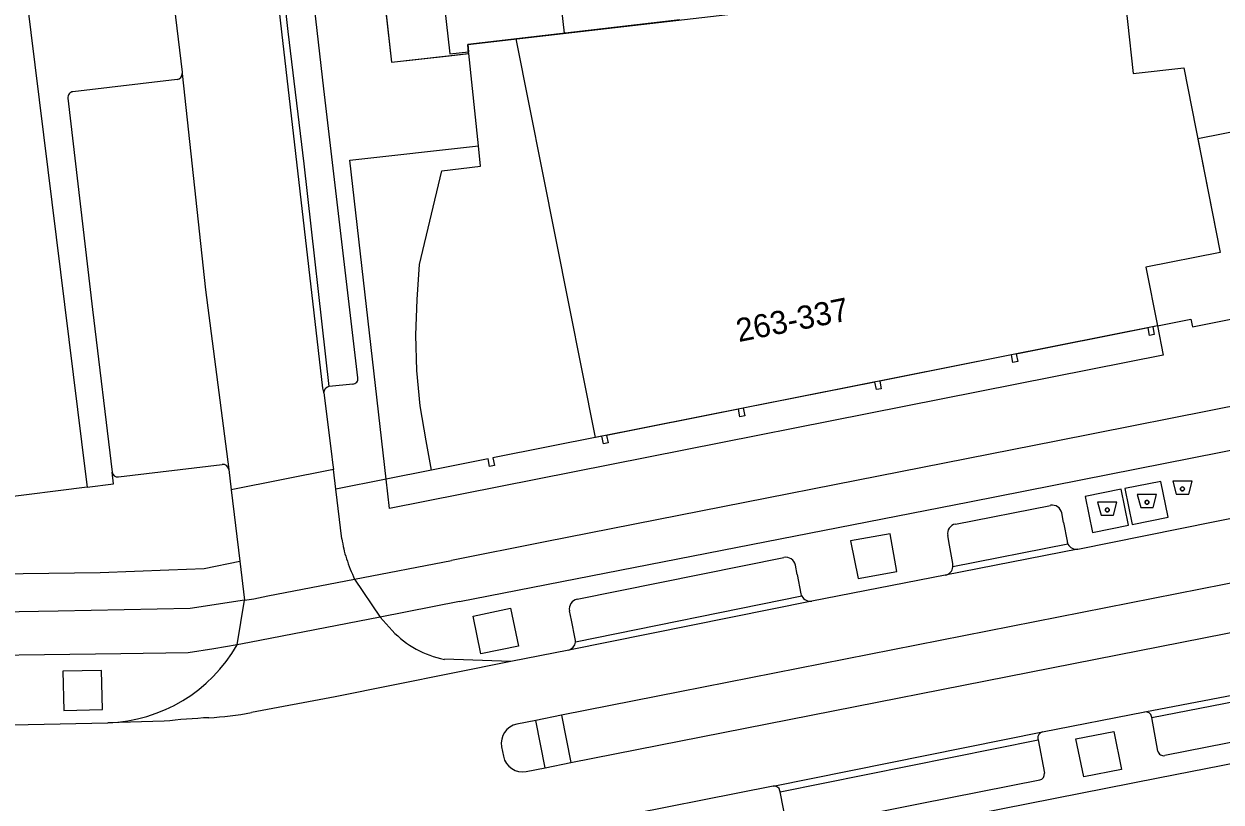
# Model space of a CAD drawing. Extents: x 194485 to 197793, y 468269 to 470822.
# Drawn here: x 194929.3 to 194991.2, y 469431.3 to 469471.6 of the extents above; entities that cross this region are included whole.
import ezdxf

# ---------------------------------------------------------------- set-up
doc = ezdxf.new("R2010")
doc.units = 0
for name, color, linetype in [('BGT begrenzing pand op maaiveld onder overbouw', 7, 'Continuous'), ('BGT grensvlak onbegroeid terreindeel', 7, 'Continuous'), ('BGT grensvlak pand deel overbouw', 7, 'Continuous'), ('BGT grensvlak pand min 1', 7, 'Continuous'), ('BGT grensvlak pand op maaiveld', 7, 'Continuous'), ('BGT grensvlak pand op maaiveld LR', 7, 'Continuous'), ('BGT grensvlak wegdeel', 7, 'Continuous'), ('BGT puntobject bak afval apart plaats', 7, 'Continuous'), ('BGT puntobject bak container', 7, 'Continuous'), ('BGT tekst huisnummerreeks', 7, 'Continuous'), ('GEM grensvlak WOZ_BRK percelen', 7, 'Continuous')]:
    doc.layers.add(name, color=color, linetype=linetype)

msp = doc.modelspace()

# ---------------------------------------------------------------- linework, layer by layer
at = {"layer": 'BGT begrenzing pand op maaiveld onder overbouw'}
for points in [[(194950.361, 469448.517), (194950.079, 469450.033), (194949.768, 469451.838), (194949.59, 469453.666), (194949.552, 469455.509), (194949.617, 469457.349), (194949.729, 469459.155), (194950.897, 469464.015), (194952.893, 469464.243), (194952.782, 469465.307)], [(194987.908, 469455.976), (194987.662, 469455.927), (194987.74, 469455.535), (194987.495, 469455.486), (194987.417, 469455.878), (194980.6, 469454.524), (194980.678, 469454.132), (194980.433, 469454.083), (194980.355, 469454.475), (194973.538, 469453.121), (194973.616, 469452.729), (194973.371, 469452.68), (194973.293, 469453.072), (194966.476, 469451.718), (194966.554, 469451.326), (194966.309, 469451.277), (194966.231, 469451.669), (194959.414, 469450.315), (194959.492, 469449.923), (194959.247, 469449.874), (194959.169, 469450.266), (194953.529, 469449.146), (194953.607, 469448.754), (194953.362, 469448.705), (194953.284, 469449.097), (194950.361, 469448.517)]]:
    msp.add_lwpolyline(points, dxfattribs=at)
at = {"layer": 'BGT grensvlak onbegroeid terreindeel'}
for points in [[(194986.593, 469445.695), (194988.456, 469446.071), (194988.08, 469447.933), (194986.218, 469447.557), (194986.593, 469445.695)], [(194984.545, 469445.281), (194986.407, 469445.657), (194986.031, 469447.52), (194984.169, 469447.144), (194984.545, 469445.281)], [(194972.023, 469444.859), (194972.426, 469442.909), (194974.419, 469443.273), (194974.083, 469445.219), (194972.023, 469444.859)], [(194952.514, 469440.961), (194954.435, 469441.364), (194954.85, 469439.402), (194952.901, 469438.998), (194952.514, 469440.961)], [(194931.277, 469438.107), (194931.328, 469436.071), (194933.336, 469436.12), (194933.291, 469438.134), (194931.277, 469438.107)], [(194983.687, 469434.595), (194985.65, 469434.987), (194986.047, 469433.01), (194984.093, 469432.632), (194983.687, 469434.595)]]:
    msp.add_lwpolyline(points, dxfattribs=at)
at = {"layer": 'BGT grensvlak pand deel overbouw'}
for points in [[(194948.009, 469448.049), (194946.125, 469464.553), (194952.782, 469465.307)], [(194987.908, 469455.976), (194988.2, 469454.474), (194948.183, 469446.526), (194948.009, 469448.049)]]:
    msp.add_lwpolyline(points, dxfattribs=at)
at = {"layer": 'BGT grensvlak pand min 1'}
msp.add_lwpolyline([(195136.748, 469494.684), (194989.988, 469465.668), (194991.149, 469459.781), (194987.304, 469459.017), (194987.908, 469455.979), (194958.837, 469450.201), (194954.733, 469470.846), (194957.233, 469471.136), (194948.757, 469545.418), (194942.798, 469544.743), (194941.933, 469552.333), (194938.82, 469551.976), (194935.239, 469583.018)], dxfattribs=at)
at = {"layer": 'BGT grensvlak pand op maaiveld'}
for p, q in [((194927.461, 469488.652), (194932.479, 469448.163)), ((194952.284, 469470.079), (194952.274, 469470.175)), ((194952.782, 469465.307), (194952.284, 469470.079)), ((194987.908, 469455.979), (194987.908, 469455.976)), ((194932.479, 469448.163), (194932.545, 469447.628)), ((194932.545, 469447.628), (194908.627, 469444.663))]:
    msp.add_line(p, q, dxfattribs=at)
for points in [[(194950.736, 469475.097), (194951.31, 469470.065), (194952.274, 469470.175)], [(194986.063, 469474.452), (194986.645, 469469.052), (194989.264, 469469.342), (194991.149, 469459.781), (194987.304, 469459.017), (194987.908, 469455.979)]]:
    msp.add_lwpolyline(points, dxfattribs=at)
at = {"layer": 'BGT grensvlak pand op maaiveld LR'}
msp.add_lwpolyline([(194963.199, 469471.827), (194952.234, 469470.557), (194952.274, 469470.175)], dxfattribs=at)
at = {"layer": 'BGT grensvlak wegdeel'}
for p, q in [((194937.198, 469468.737), (194931.807, 469468.103)), ((194978.189, 469446.865), (195042.044, 469459.548)), ((195031.663, 469459.731), (194982.674, 469450.019)), ((194944.888, 469452.763), (194944.841, 469452.707)), ((194944.966, 469452.815), (194944.888, 469452.763)), ((194945.037, 469452.838), (194944.966, 469452.815)), ((194944.803, 469452.623), (194944.79, 469452.543)), ((194944.793, 469452.515), (194944.79, 469452.543)), ((194944.822, 469452.673), (194944.803, 469452.623)), ((194944.832, 469452.692), (194944.822, 469452.673)), ((194944.841, 469452.707), (194944.832, 469452.692)), ((194982.674, 469450.019), (194956.234, 469444.794)), ((194934.161, 469448.159), (194939.532, 469448.807)), ((194939.866, 469448.547), (194939.992, 469447.492)), ((194945.279, 469448.555), (194939.992, 469447.492)), ((194945.405, 469447.532), (194945.279, 469448.555)), ((194950.361, 469448.517), (194948.009, 469448.049)), ((194948.009, 469448.049), (194945.405, 469447.532)), ((194939.992, 469447.492), (194940.436, 469443.796)), ((194945.721, 469444.961), (194945.405, 469447.532)), ((194951.8, 469441.713), (194978.189, 469446.865)), ((194977.451, 469445.722), (194982.368, 469446.691)), ((194983.053, 469445.801), (194982.955, 469446.297)), ((194983.786, 469444.422), (194992.604, 469446.202)), ((194983.053, 469445.801), (194983.23, 469444.834)), ((194956.234, 469444.794), (194951.391, 469443.833)), ((194977.156, 469444.631), (194977.057, 469445.134)), ((194983.786, 469444.422), (194976.931, 469443.071)), ((194977.313, 469443.686), (194977.156, 469444.631)), ((194983.278, 469444.679), (194977.325, 469443.505)), ((194940.436, 469443.796), (194940.679, 469441.777)), ((194946.377, 469442.866), (194951.391, 469443.833)), ((194957.884, 469441.826), (194968.586, 469443.991)), ((194969.275, 469443.108), (194969.176, 469443.6)), ((194903.767, 469442.871), (194933.219, 469443.214)), ((194941.881, 469441.999), (194946.377, 469442.866)), ((194946.377, 469442.866), (194947.704, 469440.91)), ((194994.298, 469443.178), (194957.084, 469435.822)), ((194969.275, 469443.108), (194969.465, 469442.114)), ((194976.931, 469443.071), (194970.029, 469441.732)), ((194940.303, 469439.47), (194940.679, 469441.777)), ((194940.679, 469441.777), (194941.164, 469441.859)), ((194941.164, 469441.859), (194941.881, 469441.999)), ((194951.8, 469441.713), (194947.704, 469440.91)), ((194970.029, 469441.732), (194957.455, 469439.19)), ((194969.512, 469441.984), (194957.795, 469439.615)), ((194957.594, 469440.739), (194957.493, 469441.237)), ((194947.704, 469440.91), (194940.94, 469439.583)), ((194948.325, 469440.206), (194947.704, 469440.91)), ((194957.569, 469433.37), (194994.77, 469440.723)), ((194957.782, 469439.777), (194957.594, 469440.739)), ((194940.94, 469439.583), (194940.303, 469439.47)), ((194957.455, 469439.19), (194954.452, 469438.604)), ((194954.452, 469438.604), (194945.372, 469436.774)), ((194954.452, 469438.604), (194951.019, 469438.719)), ((194987.247, 469435.993), (194995.363, 469437.566)), ((194945.372, 469436.774), (194941.042, 469435.968)), ((194987.609, 469435.707), (194995.143, 469437.167)), ((194936.524, 469435.513), (194933.612, 469435.437)), ((194955.75, 469435.558), (194954.769, 469435.364)), ((194957.084, 469435.822), (194955.75, 469435.558)), ((194956.236, 469433.106), (194955.75, 469435.558)), ((194957.084, 469435.822), (194957.569, 469433.37)), ((194987.609, 469435.707), (194987.6, 469435.754)), ((194987.932, 469433.973), (194987.609, 469435.707)), ((194968.023, 469432.151), (194981.957, 469434.959)), ((194995.166, 469435.104), (194988.285, 469433.734)), ((194953.982, 469434.189), (194954.079, 469433.699)), ((194968.386, 469431.867), (194981.733, 469434.557)), ((194981.723, 469434.61), (194981.733, 469434.557)), ((194981.733, 469434.557), (194982.056, 469432.822)), ((194955.255, 469432.912), (194956.236, 469433.106)), ((194956.236, 469433.106), (194957.569, 469433.37)), ((194968.386, 469431.867), (194968.376, 469431.915)), ((194968.72, 469430.181), (194968.386, 469431.867))]:
    msp.add_line(p, q, dxfattribs=at)
for points in [[(194942.8, 469544.724), (194939.825, 469544.405), (194939.886, 469543.859), (194948.292, 469469.627), (194951.273, 469469.965), (194952.284, 469470.079)], [(194946.546, 469453.293), (194944.778, 469468.253), (194941.389, 469498.021), (194938.256, 469525.296)], [(194944.79, 469452.543), (194944.734, 469452.757), (194942.605, 469471.203), (194936.494, 469525.096)], [(194936.834, 469525.135), (194938.66, 469508.895), (194940.18, 469495.711), (194942.923, 469471.215), (194943.743, 469464.369), (194945.037, 469452.838)], [(194935.018, 469490.023), (194935.079, 469489.532), (194936.303, 469478.68), (194937.453, 469469.124), (194937.459, 469469.07), (194937.462, 469469.04)], [(194937.462, 469469.04), (194938.655, 469457.854), (194939.866, 469448.547)], [(194931.544, 469467.77), (194932.815, 469456.823), (194933.828, 469448.409)], [(194987.908, 469455.979), (194989.641, 469456.323), (194989.719, 469455.928), (194994.226, 469456.824), (194993.712, 469459.43), (194999.18, 469460.51)], [(194946.283, 469452.965), (194945.052, 469452.841), (194945.037, 469452.838)], [(194944.793, 469452.515), (194945.182, 469449.353), (194945.236, 469448.907), (194945.279, 469448.555)], [(194932.545, 469447.628), (194933.902, 469447.796), (194933.828, 469448.409)], [(194933.219, 469443.214), (194936.768, 469443.356), (194938.589, 469443.429), (194940.436, 469443.796)], [(194940.679, 469441.777), (194937.877, 469441.347), (194931.041, 469441.21), (194916.853, 469440.974), (194907.42, 469440.847), (194903.956, 469440.821)], [(194940.303, 469439.47), (194939.093, 469439.255), (194937.774, 469439.059), (194934.276, 469439.001), (194923.731, 469438.873), (194911.39, 469438.721), (194907.975, 469438.666)], [(195007.951, 469436.518), (194998.678, 469434.67), (194987.936, 469432.574), (194977.209, 469430.449), (194968.563, 469428.751), (194959.633, 469426.985), (194953.449, 469425.75)], [(194928.48, 469435.336), (194929.497, 469435.352), (194933.612, 469435.437)], [(194981.957, 469434.959), (194981.958, 469434.959), (194987.247, 469435.993)], [(194969.073, 469429.946), (194975.64, 469431.254), (194981.819, 469432.473)], [(194968.023, 469432.151), (194958.977, 469430.354), (194958.196, 469430.197), (194957.1, 469429.992), (194956.233, 469429.818), (194952.105, 469428.985), (194951.233, 469428.823)]]:
    msp.add_lwpolyline(points, dxfattribs=at)
for centre, radius, start, end in [((194937.161, 469469.036), 0.301, 277.04859, 0.82098), ((194931.837, 469467.809), 0.295, 95.77455, 187.62281), ((194946.263, 469453.25), 0.286, 273.97245, 8.58023), ((194934.12, 469448.451), 0.295, 188.16803, 278.03713), ((194939.566, 469448.507), 0.302, 7.68902, 96.51352), ((194982.464, 469446.2), 0.501, 11.201, 101.05922), ((194977.548, 469445.231), 0.5, 101.13989, 191.21056), ((194950.901, 469445.603), 5.22, 187.06115, 198.70092), ((194983.711, 469444.898), 0.485, 187.57225, 206.84089), ((194983.707, 469444.896), 0.48, 206.81079, 279.51901), ((194956.649, 469447.539), 11.285, 198.65671, 204.46205), ((194968.685, 469443.5), 0.501, 11.54555, 101.38863), ((194976.824, 469443.564), 0.504, 282.20636, 353.32517), ((194976.82, 469443.562), 0.509, 353.5216, 14.06452), ((194957.983, 469441.336), 0.5, 101.37695, 191.46769), ((194969.943, 469442.213), 0.489, 191.74677, 208.00697), ((194969.943, 469442.213), 0.488, 207.9284, 280.09985), ((194951.952, 469443.593), 4.963, 223.04254, 259.16293), ((194957.29, 469439.656), 0.507, 355.35809, 13.81786), ((194933.355, 469443.43), 7.997, 271.8417, 330.31724), ((194957.303, 469439.66), 0.494, 287.92513, 354.75525), ((194941.145, 469392.229), 43.53, 93.03256, 96.09367), ((194938.042, 469451.316), 15.639, 272.93299, 281.06054), ((194987.304, 469435.696), 0.302, 11.00729, 100.79248), ((194954.964, 469434.382), 1.001, 101.245, 191.12765), ((194982.017, 469434.666), 0.299, 101.51684, 190.80047), ((194955.061, 469433.894), 1.001, 191.21494, 281.20278), ((194988.227, 469434.029), 0.301, 190.75086, 281.04891), ((194981.76, 469432.768), 0.301, 281.27251, 10.36797), ((194968.081, 469431.856), 0.301, 11.37331, 101.09686)]:
    msp.add_arc(centre, radius, start, end, dxfattribs=at)
at = {"layer": 'BGT puntobject bak afval apart plaats'}
for points in [[(194987.688, 469446.575), (194987.863, 469447.25), (194986.863, 469447.25), (194987.038, 469446.575)], [(194985.636, 469446.179), (194985.811, 469446.854), (194984.811, 469446.854), (194984.986, 469446.179)]]:
    msp.add_lwpolyline(points, close=True, dxfattribs=at)
for centre in [(194985.311, 469446.454), (194987.363, 469446.85)]:
    msp.add_circle(centre, 0.1, dxfattribs=at)
for centre, start, end in [((194985.311, 469446.454), 0, 180), ((194987.363, 469446.85), 0, 180), ((194987.363, 469446.85), 180, 0), ((194985.311, 469446.454), 180, 0)]:
    msp.add_arc(centre, 0.1, start, end, dxfattribs=at)
at = {"layer": 'BGT puntobject bak container'}
msp.add_lwpolyline([(194989.522, 469447.266), (194989.697, 469447.941), (194988.697, 469447.941), (194988.872, 469447.266)], close=True, dxfattribs=at)
msp.add_circle((194989.197, 469447.541), 0.1, dxfattribs=at)
for start, end in [(0, 180), (180, 0)]:
    msp.add_arc((194989.197, 469447.541), 0.1, start, end, dxfattribs=at)
at = {"layer": 'GEM grensvlak WOZ_BRK percelen'}
msp.add_lwpolyline([(194947.711, 469474.755), (194948.292, 469469.627), (194952.272, 469470.078), (194952.234, 469470.557), (194975.1, 469473.205)], dxfattribs=at)

# ---------------------------------------------------------------- texts
at = {"layer": 'BGT tekst huisnummerreeks'}
msp.add_text('263-337', height=1.2, rotation=11.2, dxfattribs=at).set_placement((194966.242, 469455.14))

doc.saveas('drawing.dxf')
